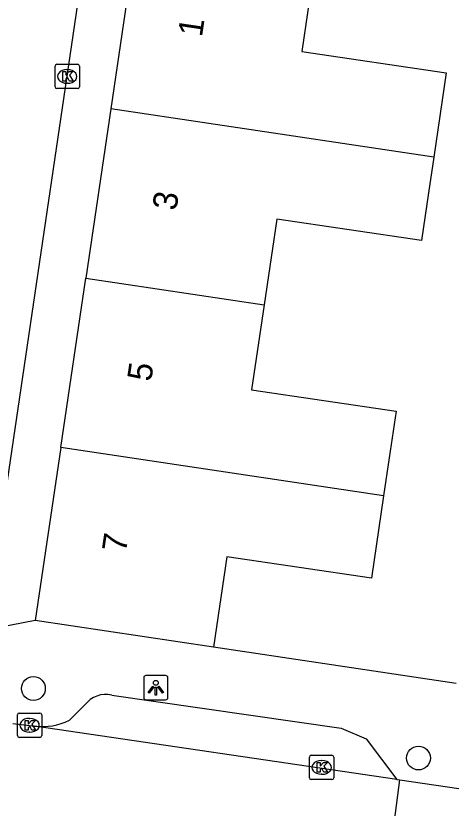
# Model space of a CAD drawing. Extents: x 163686 to 164493, y 382719 to 383870.
# Drawn here: x 164000.67 to 164018.55, y 383055.9 to 383088.49 of the extents above; entities that cross this region are included whole.
import ezdxf

# ---------------------------------------------------------------- set-up
doc = ezdxf.new("R2010")
doc.units = 0
for name, color, linetype in [('IMGEO_Boom', 7, 'Continuous'), ('IMGEO_Kolk', 7, 'Continuous'), ('IMGEO_Lichtpunt', 7, 'Continuous'), ('IMGEO_Pand', 7, 'Continuous'), ('IMGEO_Pand_nummerreeks', 7, 'Continuous'), ('IMGEO_Rijbaan_lokaal_open', 7, 'Continuous'), ('IMGEO_Voetpad_open', 7, 'Continuous')]:
    doc.layers.add(name, color=color, linetype=linetype)

msp = doc.modelspace()

# ---------------------------------------------------------------- linework, layer by layer
at = {"layer": 'IMGEO_Boom'}
for centre in [(164001.387, 383060.819), (164017.204, 383057.959)]:
    msp.add_circle(centre, 0.489, dxfattribs=at)
at = {"layer": 'IMGEO_Kolk'}
for p, q in [((164002.275, 383085.569), (164002.275, 383086.421)), ((164002.35, 383086.495), (164003.202, 383086.495)), ((164002.763, 383086.275), (164002.788, 383086.275)), ((164003.276, 383086.421), (164003.276, 383085.569)), ((164002.786, 383085.715), (164002.761, 383085.715)), ((164003.202, 383085.495), (164002.35, 383085.495)), ((164000.729, 383058.882), (164000.729, 383059.734)), ((164000.804, 383059.808), (164001.656, 383059.808)), ((164001.217, 383059.588), (164001.242, 383059.588)), ((164001.73, 383059.734), (164001.73, 383058.882)), ((164001.24, 383059.028), (164001.215, 383059.028)), ((164001.656, 383058.808), (164000.804, 383058.808)), ((164012.726, 383057.146), (164012.726, 383057.998)), ((164012.801, 383058.072), (164013.653, 383058.072)), ((164013.727, 383057.998), (164013.727, 383057.146)), ((164013.214, 383057.852), (164013.239, 383057.852)), ((164013.237, 383057.292), (164013.212, 383057.292)), ((164013.653, 383057.072), (164012.801, 383057.072))]:
    msp.add_line(p, q, dxfattribs=at)
for points in [[(164002.275, 383085.569), (164002.275, 383086.421)], [(164002.35, 383086.495), (164003.202, 383086.495)], [(164003.276, 383086.421), (164003.276, 383085.569)], [(164002.596, 383086.195), (164002.719, 383086.195), (164002.719, 383086.044), (164002.849, 383086.195), (164003.013, 383086.195), (164002.867, 383086.044), (164003.02, 383085.795), (164002.868, 383085.795), (164002.783, 383085.959), (164002.719, 383085.892), (164002.719, 383085.795), (164002.596, 383085.795), (164002.596, 383086.195)], [(164003.202, 383085.495), (164002.35, 383085.495)], [(164000.729, 383058.882), (164000.729, 383059.734)], [(164000.804, 383059.808), (164001.656, 383059.808)], [(164001.73, 383059.734), (164001.73, 383058.882)], [(164001.05, 383059.508), (164001.173, 383059.508), (164001.173, 383059.357), (164001.303, 383059.508), (164001.467, 383059.508), (164001.321, 383059.357), (164001.474, 383059.108), (164001.322, 383059.108), (164001.237, 383059.272), (164001.173, 383059.205), (164001.173, 383059.108), (164001.05, 383059.108), (164001.05, 383059.508)], [(164001.656, 383058.808), (164000.804, 383058.808)], [(164012.726, 383057.146), (164012.726, 383057.998)], [(164012.801, 383058.072), (164013.653, 383058.072)], [(164013.727, 383057.998), (164013.727, 383057.146)], [(164013.047, 383057.772), (164013.17, 383057.772), (164013.17, 383057.621), (164013.3, 383057.772), (164013.464, 383057.772), (164013.318, 383057.621), (164013.471, 383057.372), (164013.319, 383057.372), (164013.234, 383057.536), (164013.17, 383057.469), (164013.17, 383057.372), (164013.047, 383057.372), (164013.047, 383057.772)], [(164013.653, 383057.072), (164012.801, 383057.072)]]:
    msp.add_lwpolyline(points, dxfattribs=at)
for centre, start, end in [((164002.352, 383086.419), 91.552, 178.448), ((164002.352, 383086.419), 91.552, 178.448), ((164003.2, 383086.419), 1.552, 88.448), ((164003.2, 383086.419), 1.552, 88.448), ((164002.352, 383085.571), 181.552, 268.448), ((164002.352, 383085.571), 181.552, 268.448), ((164003.2, 383085.571), 271.552, 358.448), ((164003.2, 383085.571), 271.552, 358.448), ((164000.806, 383059.732), 91.552, 178.448), ((164000.806, 383059.732), 91.552, 178.448), ((164001.654, 383059.732), 1.552, 88.448), ((164001.654, 383059.732), 1.552, 88.448), ((164000.806, 383058.884), 181.552, 268.448), ((164000.806, 383058.884), 181.552, 268.448), ((164001.654, 383058.884), 271.552, 358.448), ((164001.654, 383058.884), 271.552, 358.448), ((164012.803, 383057.996), 91.552, 178.448), ((164012.803, 383057.996), 91.552, 178.448), ((164013.651, 383057.996), 1.552, 88.448), ((164013.651, 383057.996), 1.552, 88.448), ((164012.803, 383057.148), 181.552, 268.448), ((164012.803, 383057.148), 181.552, 268.448), ((164013.651, 383057.148), 271.552, 358.448), ((164013.651, 383057.148), 271.552, 358.448)]:
    msp.add_arc(centre, 0.0765, start, end, dxfattribs=at)
for centre, major_axis, ratio, start_param, end_param in [((164002.762, 383085.995), (-0.387, 0.002), 0.722429, 4.712389, 7.853982), ((164002.787, 383085.995), (-0.39, 0.002), 0.717154, 1.570796, 4.712389), ((164001.216, 383059.308), (-0.387, 0.002), 0.722429, 4.712389, 7.853982), ((164001.241, 383059.308), (-0.39, 0.002), 0.717154, 1.570796, 4.712389), ((164013.213, 383057.572), (-0.387, 0.002), 0.722429, 4.712389, 7.853982), ((164013.238, 383057.572), (-0.39, 0.002), 0.717154, 1.570796, 4.712389)]:
    msp.add_ellipse(centre, major_axis=major_axis, ratio=ratio, start_param=start_param, end_param=end_param, dxfattribs=at)
at = {"layer": 'IMGEO_Lichtpunt'}
for p, q in [((164005.918, 383061.256), (164005.918, 383060.449)), ((164005.918, 383061.256), (164005.918, 383060.449)), ((164006.82, 383061.351), (164006.012, 383061.351)), ((164006.82, 383061.351), (164006.012, 383061.351)), ((164006.914, 383060.449), (164006.914, 383061.256)), ((164006.914, 383060.449), (164006.914, 383061.256)), ((164006.012, 383060.355), (164006.82, 383060.355)), ((164006.012, 383060.355), (164006.82, 383060.355))]:
    msp.add_line(p, q, dxfattribs=at)
for points in [[(164006.292, 383060.92), (164006.331, 383060.892), (164006.143, 383060.63), (164006.105, 383060.657), (164006.292, 383060.92)], [(164006.394, 383060.872), (164006.441, 383060.872), (164006.441, 383060.55), (164006.394, 383060.55), (164006.394, 383060.872)], [(164006.504, 383060.892), (164006.542, 383060.919), (164006.729, 383060.657), (164006.69, 383060.629), (164006.504, 383060.892)]]:
    msp.add_lwpolyline(points, dxfattribs=at)
msp.add_circle((164006.417, 383061.054), 0.0994, dxfattribs=at)
for centre, start, end in [((164006.012, 383061.256), 90, 180), ((164006.012, 383061.256), 90, 180), ((164006.82, 383061.256), 0, 90), ((164006.82, 383061.256), 0, 90), ((164006.012, 383060.449), 180, 270), ((164006.012, 383060.449), 180, 270), ((164006.82, 383060.449), 270, 0), ((164006.82, 383060.449), 270, 360)]:
    msp.add_arc(centre, 0.0946, start, end, dxfattribs=at)
at = {"layer": 'IMGEO_Pand'}
for points in [[(164005.606, 383091.746), (164004.564, 383084.669)], [(164012.951, 383090.682), (164012.41, 383087.025), (164018.347, 383086.148), (164017.834, 383082.676)], [(164004.564, 383084.669), (164003.538, 383077.702)], [(164017.834, 383082.676), (164004.564, 383084.669)], [(164017.834, 383082.676), (164017.616, 383081.202), (164017.328, 383079.253), (164011.392, 383080.13), (164010.87, 383076.601)], [(164002.512, 383070.735), (164003.538, 383077.702)], [(164003.538, 383077.702), (164010.87, 383076.601)], [(164010.87, 383076.601), (164010.353, 383073.107), (164016.29, 383072.23), (164016.005, 383070.301), (164015.775, 383068.743)], [(164002.512, 383070.735), (164001.464, 383063.621)], [(164015.775, 383068.743), (164002.512, 383070.735)], [(164015.775, 383068.743), (164015.274, 383065.354), (164009.338, 383066.231), (164008.789, 383062.521)], [(164008.789, 383062.521), (164001.464, 383063.621)]]:
    msp.add_lwpolyline(points, dxfattribs=at)
at = {"layer": 'IMGEO_Rijbaan_lokaal_open'}
for points in [[(163999.41, 383063.224), (164000, 383067.22), (164003.533, 383091.132)], [(164000.537, 383059.386), (164001.229, 383059.295), (164001.439, 383059.264)], [(164016.315, 383057.077), (164001.439, 383059.264)], [(164015.819, 383052.322), (164016.437, 383057.059)], [(164016.315, 383057.077), (164016.437, 383057.059)], [(164016.437, 383057.059), (164022.215, 383056.211)]]:
    msp.add_lwpolyline(points, dxfattribs=at)
at = {"layer": 'IMGEO_Voetpad_open'}
for points in [[(164001.464, 383063.621), (163999.41, 383063.224)], [(164018.747, 383061.027), (164008.789, 383062.521)], [(164004.603, 383060.549), (164014.034, 383059.188), (164015.06, 383058.752), (164016.315, 383057.077)], [(164002.866, 383059.517), (164003.504, 383060.143)]]:
    msp.add_lwpolyline(points, dxfattribs=at)
for centre, radius, start, end in [((164004.363, 383059.507), 1.069, 77.0451, 143.506), ((164001.716, 383061.85), 2.601, 263.8744, 296.2331)]:
    msp.add_arc(centre, radius, start, end, dxfattribs=at)

# ---------------------------------------------------------------- texts
at = {"layer": 'IMGEO_Pand_nummerreeks'}
for s, p in [('1', (164008.31, 383087.593)), ('3', (164007.258, 383080.449)), ('5', (164006.222, 383073.417)), ('7', (164005.187, 383066.386))]:
    msp.add_text(s, height=1, rotation=81.6222, dxfattribs=at).set_placement(p)

doc.saveas('drawing.dxf')
